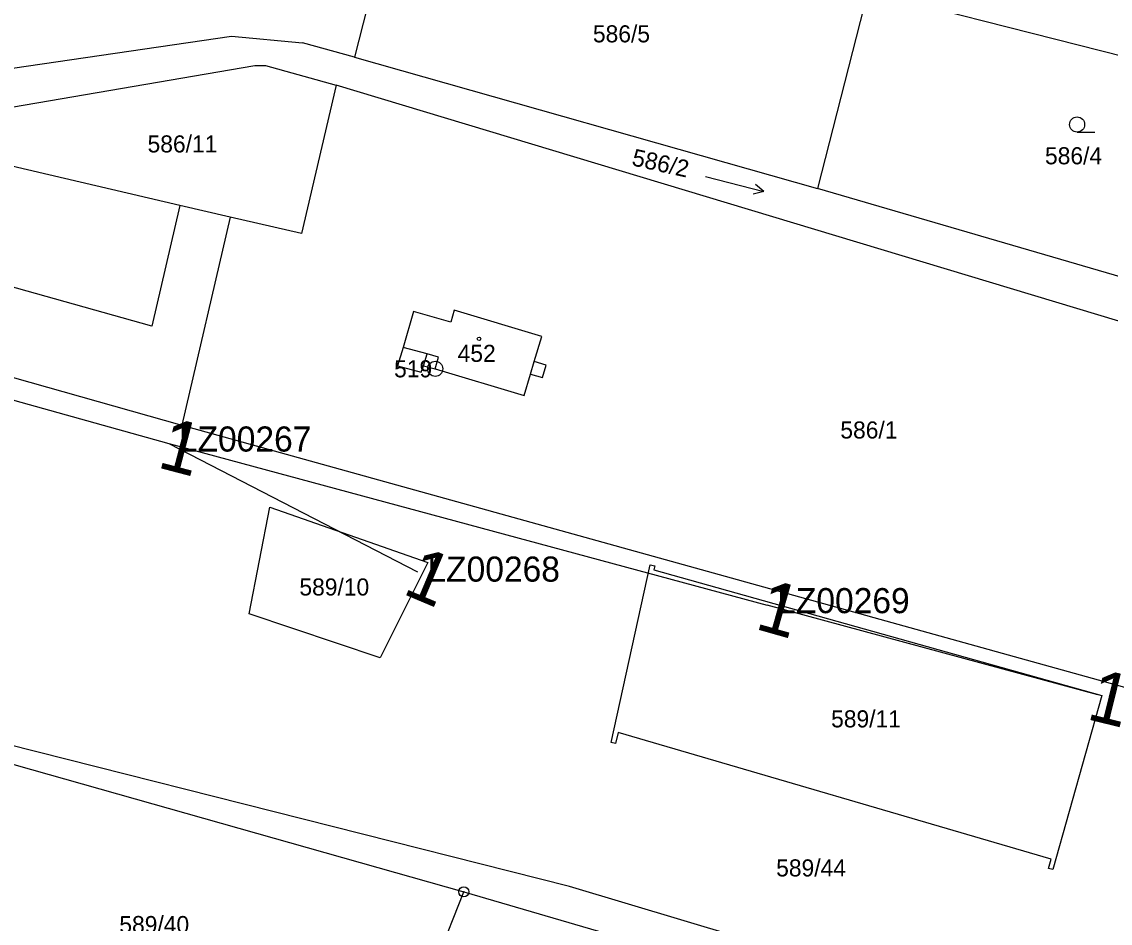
# Model space of a CAD drawing. Extents: x -738131 to -734179, y -1033447 to -1030078.
# Drawn here: x -735849.9 to -735741.5, y -1032166.9 to -1032077.2 of the extents above; entities that cross this region are included whole.
import ezdxf

# ---------------------------------------------------------------- set-up
doc = ezdxf.new("R2010")
doc.units = 0
for name, color, linetype in [('ftf_2010', 7, 'Continuous'), ('ftf_2050', 7, 'Continuous'), ('ftf_2080', 7, 'Continuous'), ('ftf_3010', 7, 'Continuous'), ('ftf_3010_ftf_3010_gtda_3015_gtda_3015_1', 7, 'Continuous'), ('Vrstva 1', 7, 'Continuous'), ('Vrstva 2', 7, 'Continuous'), ('Vrstva 3', 7, 'Continuous'), ('Vrstva 4', 7, 'Continuous'), ('Vrstva 5', 7, 'Continuous'), ('Vrstva 8', 7, 'Continuous')]:
    doc.layers.add(name, color=color, linetype=linetype)

msp = doc.modelspace()

# ---------------------------------------------------------------- linework, layer by layer
at = {"layer": 'ftf_2010'}
for points in [[(-735835.25, -1032119.17), (-735775.67, -1032135.26)], [(-735742.74, -1032144.21), (-735775.67, -1032135.26)]]:
    msp.add_lwpolyline(points, dxfattribs=at)
at = {"layer": 'ftf_2050'}
msp.add_lwpolyline([(-735864.77, -1032110.93), (-735835.25, -1032119.17)], dxfattribs=at)
at = {"layer": 'ftf_2080'}
msp.add_lwpolyline([(-735835.25, -1032119.17), (-735810.5, -1032131.94)], dxfattribs=at)
at = {"layer": 'Vrstva 1'}
for points in [[(-735812.08, -1032062.32), (-735816.76, -1032080.72)], [(-735765.65, -1032074.13), (-735770.65, -1032093.79)], [(-735765.65, -1032074.13), (-735723.76, -1032084.79)], [(-735855.16, -1032082.45), (-735829.02, -1032078.63)], [(-735829.02, -1032078.63), (-735821.94, -1032079.3)], [(-735816.76, -1032080.72), (-735821.94, -1032079.3)], [(-735853.29, -1032086.08), (-735826.69, -1032081.53)], [(-735826.69, -1032081.53), (-735825.62, -1032081.53)], [(-735825.62, -1032081.53), (-735818.59, -1032083.49)], [(-735816.76, -1032080.72), (-735770.65, -1032093.79)], [(-735818.59, -1032083.49), (-735822.03, -1032098.28)], [(-735725.36, -1032111.62), (-735818.59, -1032083.49)], [(-735836.94, -1032107.49), (-735895.73, -1032090.99)], [(-735834.14, -1032095.47), (-735852.48, -1032091.2)], [(-735728.55, -1032106.07), (-735770.65, -1032093.79)], [(-735834.14, -1032095.47), (-735836.94, -1032107.49)], [(-735829.14, -1032096.63), (-735834.14, -1032095.47)], [(-735829.14, -1032096.63), (-735833.96, -1032117.36)], [(-735822.03, -1032098.28), (-735829.14, -1032096.63)], [(-735810.88, -1032106.03), (-735811.92, -1032109.61)], [(-735807.18, -1032107.09), (-735810.88, -1032106.03)], [(-735806.84, -1032105.91), (-735807.18, -1032107.09)], [(-735798.12, -1032108.54), (-735806.84, -1032105.91)], [(-735864.26, -1032108.8), (-735833.96, -1032117.36)], [(-735798.86, -1032111.02), (-735798.12, -1032108.54)], [(-735811.92, -1032109.61), (-735812.47, -1032111.43)], [(-735797.66, -1032111.38), (-735798.86, -1032111.02)], [(-735812.47, -1032111.43), (-735810.13, -1032112.09)], [(-735810.13, -1032112.09), (-735809.9, -1032111.44)], [(-735809.9, -1032111.44), (-735808.72, -1032111.74)], [(-735808.72, -1032111.74), (-735799.87, -1032114.41)], [(-735798.03, -1032112.62), (-735797.66, -1032111.38)], [(-735799.87, -1032114.41), (-735799.23, -1032112.26)], [(-735799.23, -1032112.26), (-735798.03, -1032112.62)], [(-735833.96, -1032117.36), (-735734.71, -1032144.94)], [(-735827.25, -1032136.13), (-735825.19, -1032125.53)], [(-735825.19, -1032125.53), (-735809.45, -1032131.03)], [(-735809.45, -1032131.03), (-735814.2, -1032140.53)], [(-735791.2, -1032148.95), (-735787.31, -1032131.27)], [(-735787.31, -1032131.27), (-735786.86, -1032131.37)], [(-735786.86, -1032131.37), (-735786.95, -1032131.76)], [(-735786.95, -1032131.76), (-735742.35, -1032144.27)], [(-735814.2, -1032140.53), (-735827.25, -1032136.13)], [(-735795.35, -1032163.27), (-735874.95, -1032143.16)], [(-735876.65, -1032143.8), (-735805.88, -1032163.81)], [(-735742.35, -1032144.27), (-735747.21, -1032161.6)], [(-735790.76, -1032149.05), (-735791.2, -1032148.95)], [(-735790.52, -1032147.94), (-735790.76, -1032149.05)], [(-735747.38, -1032160.56), (-735790.52, -1032147.94)], [(-735747.64, -1032161.48), (-735747.38, -1032160.56)], [(-735747.21, -1032161.6), (-735747.64, -1032161.48)], [(-735826.84, -1032216.9), (-735805.88, -1032163.81)], [(-735805.88, -1032163.81), (-735747.36, -1032180.89)], [(-735756.23, -1032175), (-735795.35, -1032163.27)]]:
    msp.add_lwpolyline(points, dxfattribs=at)
at = {"layer": 'Vrstva 3'}
for p, q in [((-735744.8, -1032088.17), (-735743.05, -1032088.17)), ((-735781.81, -1032092.6), (-735776, -1032094.1)), ((-735776, -1032094.1), (-735776.82, -1032093.38)), ((-735776, -1032094.1), (-735777.07, -1032094.34))]:
    msp.add_line(p, q, dxfattribs=at)
msp.add_circle((-735744.8, -1032087.42), 0.75, dxfattribs=at)
at = {"layer": 'Vrstva 4'}
for points in [[(-735809.52, -1032110.26), (-735811.92, -1032109.61)], [(-735809.9, -1032111.44), (-735809.52, -1032110.26)], [(-735808.4, -1032110.57), (-735809.52, -1032110.26)], [(-735808.72, -1032111.74), (-735808.4, -1032110.57)], [(-735799.23, -1032112.26), (-735798.86, -1032111.02)]]:
    msp.add_lwpolyline(points, dxfattribs=at)
at = {"layer": 'Vrstva 5'}
msp.add_circle((-735804.36, -1032108.76), 0.175, dxfattribs=at)
at = {"layer": 'Vrstva 8'}
for centre, radius in [((-735808.72, -1032111.74), 0.75), ((-735808.72, -1032111.74), 0.03), ((-735805.88, -1032163.81), 0.5), ((-735805.88, -1032163.81), 0.0303)]:
    msp.add_circle(centre, radius, dxfattribs=at)

# ---------------------------------------------------------------- texts
at = {"layer": 'ftf_3010'}
for rotation, p in [(345.2816, (-735836.53, -1032121.52)), (337.1413, (-735812.1, -1032134.08)), (344.2006, (-735777, -1032137.59)), (346.1327, (-735743.99, -1032146.58))]:
    msp.add_text('1', height=5.2, rotation=rotation, dxfattribs=at).set_placement(p)
at = {"layer": 'ftf_3010_ftf_3010_gtda_3015_gtda_3015_1'}
for s, p in [('LZ00267', (-735834.25, -1032119.98)), ('LZ00268', (-735809.5, -1032132.93)), ('LZ00269', (-735774.67, -1032136.07))]:
    msp.add_text(s, height=2.5, dxfattribs=at).set_placement(p)
at = {"layer": 'Vrstva 2'}
for s, p in [('586/5', (-735793.02, -1032079.24)), ('586/11', (-735837.37, -1032090.2)), ('586/4', (-735748, -1032091.38)), ('452', (-735806.49, -1032111.05)), ('586/1', (-735768.38, -1032118.68)), ('589/10', (-735822.25, -1032134.31)), ('589/11', (-735769.3, -1032147.44)), ('589/44', (-735774.77, -1032162.28)), ('589/40', (-735840.18, -1032167.92))]:
    msp.add_text(s, height=1.7, dxfattribs=at).set_placement(p)
msp.add_text('586/2', height=1.7, rotation=347.4337, dxfattribs=at).set_placement((-735789.23, -1032091.47))
at = {"layer": 'Vrstva 8'}
msp.add_text('519', height=1.7, dxfattribs=at).set_placement((-735812.82, -1032112.59))

doc.saveas('drawing.dxf')
